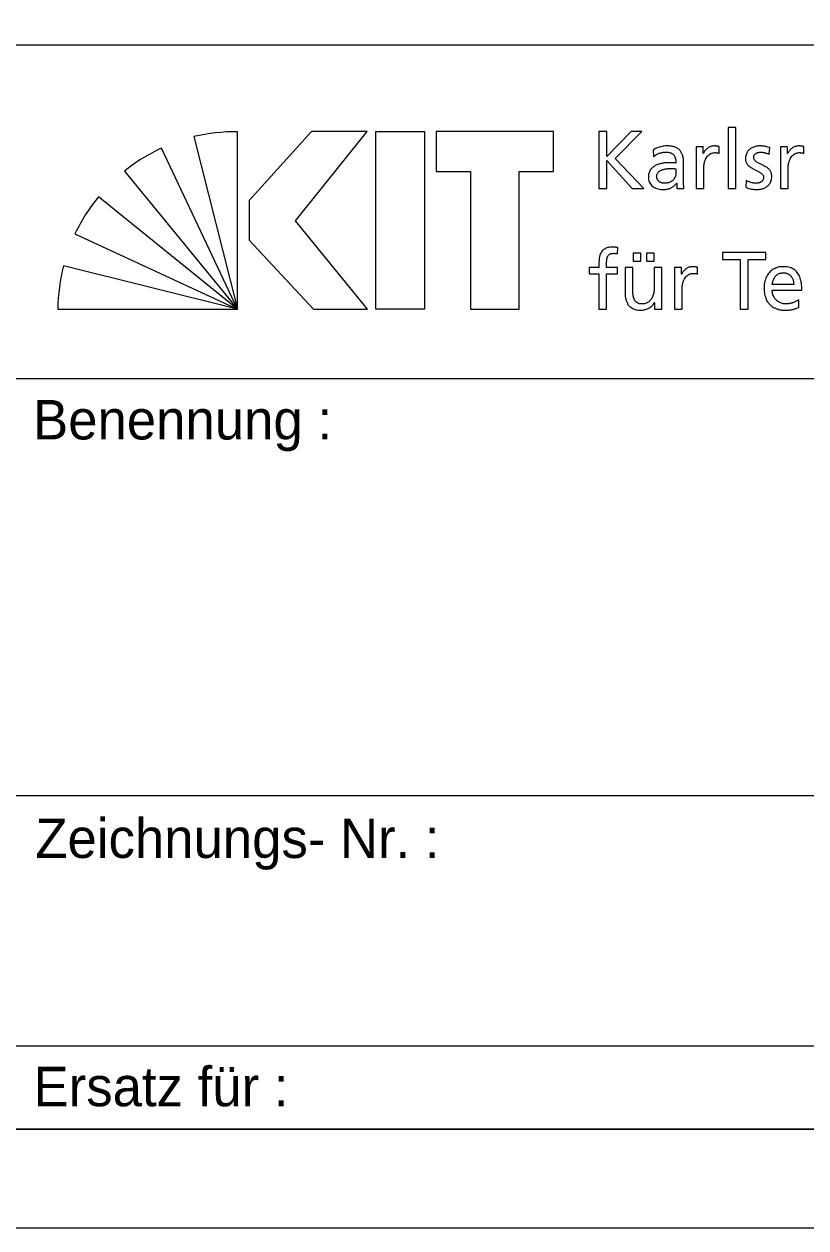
# Model space of a CAD drawing. Extents: x 0 to 11.9, y 0 to 8.4.
# Drawn here: x 11.007 to 11.403, y 0 to 0.61 of the extents above; entities that cross this region are included whole.
import ezdxf

# ---------------------------------------------------------------- set-up
doc = ezdxf.new("R2010")
doc.units = 0
doc.layers.add('90_Plankopf', color=7, linetype='Continuous')

msp = doc.modelspace()

# ---------------------------------------------------------------- linework, layer by layer
at = {"layer": '90_Plankopf'}
for p, q in [((10.0612, 0.5999), (11.84, 0.5999)), ((10.0612, 0.5999), (11.84, 0.5999)), ((11.11481, 0.46586), (11.11481, 0.55584)), ((11.2981, 0.55586), (11.2981, 0.52706)), ((11.09275, 0.55333), (11.11481, 0.46586)), ((11.11481, 0.46586), (11.07633, 0.54752)), ((11.32579, 0.54662), (11.326, 0.54332)), ((11.35926, 0.54484), (11.35926, 0.54831)), ((11.38457, 0.54439), (11.3849, 0.54778)), ((11.40211, 0.54484), (11.40211, 0.54831)), ((11.34118, 0.53118), (11.34118, 0.53989)), ((11.05744, 0.53585), (11.11481, 0.46586)), ((11.3373, 0.53709), (11.3373, 0.53523)), ((11.37297, 0.53118), (11.37277, 0.52772)), ((11.2981, 0.52706), (11.30222, 0.52706)), ((11.31506, 0.52706), (11.32108, 0.52706)), ((11.11481, 0.46586), (11.04434, 0.52286)), ((11.0324, 0.50413), (11.11481, 0.46586)), ((11.30773, 0.49393), (11.3079, 0.49706)), ((11.11481, 0.46586), (11.02658, 0.48788)), ((11.34827, 0.48365), (11.34827, 0.48712)), ((11.39706, 0.47841), (11.38616, 0.47841)), ((11.38616, 0.47552), (11.40119, 0.47552)), ((11.39958, 0.46673), (11.39958, 0.47061)), ((11.02364, 0.46586), (11.11481, 0.46586)), ((11.00001, 0.4307), (11.84, 0.4307)), ((11.00001, 0.2192), (11.84, 0.2192)), ((11.00001, 0.0923), (11.84, 0.0923)), ((11.84, 0.05), (10.0612, 0.05)), ((10.178, 0.05), (11.84, 0.05)), ((10.178, 0.05), (11.84, 0.05))]:
    msp.add_line(p, q, dxfattribs=at)
for points in [[(0, 0), (11.89, 0), (11.89, 8.41), (0, 8.41)], [(0.25, 0.05), (11.84, 0.05), (11.84, 8.36), (0.25, 8.36)], [(11.18066, 0.55586), (11.15236, 0.55586), (11.12073, 0.52099), (11.12073, 0.50092), (11.15338, 0.46586), (11.18085, 0.46586), (11.14422, 0.51063)], [(11.2097, 0.55586), (11.2097, 0.46586), (11.18501, 0.46586), (11.18501, 0.55586)], [(11.21562, 0.55586), (11.21562, 0.5356), (11.23301, 0.5356), (11.23301, 0.46586), (11.25771, 0.46586), (11.25771, 0.5356), (11.2751, 0.5356), (11.2751, 0.55586)]]:
    msp.add_lwpolyline(points, close=True, dxfattribs=at)
for points in [[(11.32108, 0.52706), (11.30647, 0.54224), (11.32001, 0.55586), (11.31452, 0.55586), (11.30222, 0.54319), (11.30222, 0.55586), (11.2981, 0.55586)], [(11.36381, 0.52706), (11.36768, 0.52706), (11.36768, 0.55801), (11.36381, 0.55801), (11.36381, 0.52706)], [(11.35122, 0.54484), (11.35113, 0.54484), (11.35113, 0.5481), (11.3475, 0.5481), (11.3475, 0.52706), (11.35138, 0.52706), (11.35138, 0.53663)], [(11.39407, 0.54484), (11.39398, 0.54484), (11.39398, 0.5481), (11.39035, 0.5481), (11.39035, 0.52706), (11.39423, 0.52706), (11.39423, 0.53663)], [(11.30222, 0.52706), (11.30222, 0.54117), (11.31506, 0.52706)], [(11.33763, 0.52978), (11.33772, 0.52978), (11.33772, 0.52706), (11.34135, 0.52706)], [(11.3699, 0.46586), (11.37403, 0.46586), (11.37403, 0.49104), (11.38298, 0.49104), (11.38298, 0.49467), (11.36094, 0.49467), (11.36094, 0.49104), (11.3699, 0.49104), (11.3699, 0.46586)], [(11.29824, 0.48885), (11.29824, 0.48691), (11.29329, 0.48691), (11.29329, 0.48378), (11.29824, 0.48378), (11.29824, 0.46586), (11.30212, 0.46586), (11.30212, 0.48378), (11.30769, 0.48378), (11.30769, 0.48691), (11.30212, 0.48691), (11.30212, 0.48918)], [(11.31554, 0.49426), (11.31554, 0.49013), (11.31942, 0.49013), (11.31942, 0.49426), (11.31554, 0.49426)], [(11.32231, 0.49426), (11.32231, 0.49013), (11.32619, 0.49013), (11.32619, 0.49426), (11.32231, 0.49426)], [(11.31542, 0.47602), (11.31542, 0.48691), (11.31154, 0.48691), (11.31154, 0.47441)], [(11.33015, 0.46586), (11.33015, 0.48691), (11.32627, 0.48691), (11.32627, 0.47717)], [(11.34022, 0.48365), (11.34014, 0.48365), (11.34014, 0.48691), (11.33651, 0.48691), (11.33651, 0.46586), (11.34039, 0.46586), (11.34039, 0.47544)], [(11.32631, 0.46921), (11.32639, 0.46921), (11.32639, 0.46586), (11.33015, 0.46586)]]:
    msp.add_lwpolyline(points, dxfattribs=at)
for centre, start, end in [((11.11449, 0.46056), 89.80527, 103.18947), ((11.11662, 0.46118), 115.01261, 128.3968), ((11.11816, 0.46263), 140.78977, 154.17397), ((11.11891, 0.46438), 165.72225, 179.10644)]:
    msp.add_arc(centre, 0.09528, start, end, dxfattribs=at)
for points in [[(11.34118, 0.53989), (11.34119, 0.5418), (11.34091, 0.54341), (11.34033, 0.5447), (11.33975, 0.54599), (11.33884, 0.54696), (11.33759, 0.54762), (11.33635, 0.54827), (11.33472, 0.5486), (11.33272, 0.5486), (11.33138, 0.54859), (11.33014, 0.54841), (11.32898, 0.54804), (11.32782, 0.54768), (11.32676, 0.54721), (11.32579, 0.54662)], [(11.326, 0.54332), (11.32653, 0.54376), (11.32713, 0.54414), (11.32779, 0.54446), (11.32846, 0.54478), (11.32916, 0.54503), (11.3299, 0.5452), (11.33063, 0.54538), (11.33137, 0.54546), (11.3321, 0.54546), (11.33339, 0.54546), (11.33441, 0.54526), (11.33518, 0.54485), (11.33594, 0.54444), (11.33649, 0.54383), (11.33682, 0.54302), (11.33715, 0.54219), (11.33731, 0.54118), (11.3373, 0.53997)], [(11.35926, 0.54831), (11.35899, 0.54837), (11.35873, 0.54841), (11.35849, 0.54846), (11.35824, 0.5485), (11.35798, 0.54854), (11.35769, 0.54856), (11.35741, 0.54859), (11.35708, 0.5486), (11.3567, 0.5486), (11.35595, 0.54859), (11.35523, 0.54843), (11.35452, 0.54811), (11.35382, 0.54779), (11.35318, 0.54736), (11.35261, 0.54679), (11.35203, 0.54623), (11.35157, 0.54558), (11.35122, 0.54484)], [(11.35138, 0.53663), (11.35139, 0.5384), (11.35163, 0.53993), (11.3521, 0.54121), (11.35257, 0.54249), (11.35323, 0.54348), (11.35409, 0.54416), (11.35494, 0.54486), (11.35595, 0.54521), (11.35712, 0.54521), (11.35746, 0.54522), (11.3578, 0.54519), (11.35818, 0.54514), (11.35855, 0.54509), (11.35891, 0.54499), (11.35926, 0.54484)], [(11.3849, 0.54778), (11.38414, 0.54801), (11.38337, 0.5482), (11.38259, 0.54836), (11.38181, 0.54851), (11.38097, 0.54859), (11.38007, 0.5486), (11.37903, 0.5486), (11.37805, 0.54847), (11.37716, 0.5482), (11.37625, 0.54794), (11.37547, 0.54753), (11.3748, 0.547), (11.37412, 0.54647), (11.37359, 0.54579), (11.37322, 0.54498), (11.37284, 0.54417), (11.37265, 0.54321), (11.37264, 0.54212), (11.37265, 0.54128), (11.37282, 0.54056), (11.37315, 0.53994), (11.37347, 0.53933), (11.37391, 0.5388), (11.37445, 0.53834), (11.375, 0.5379), (11.37559, 0.5375), (11.37623, 0.53715), (11.37688, 0.5368), (11.37753, 0.53647), (11.37817, 0.53617), (11.37882, 0.53586), (11.37942, 0.53555), (11.37995, 0.53522), (11.3805, 0.5349), (11.38093, 0.53454), (11.38126, 0.53413), (11.38158, 0.53373), (11.38176, 0.53325), (11.38176, 0.53271), (11.38176, 0.53215), (11.38163, 0.53167), (11.38139, 0.53128), (11.38116, 0.5309), (11.38084, 0.53059), (11.38045, 0.53035), (11.38006, 0.53012), (11.37963, 0.52995), (11.37917, 0.52985), (11.37871, 0.52975), (11.37825, 0.5297), (11.3778, 0.5297), (11.37742, 0.5297), (11.37695, 0.52975), (11.37639, 0.52986), (11.37584, 0.52997), (11.37526, 0.53014), (11.37466, 0.53036), (11.37405, 0.53058), (11.3735, 0.53085), (11.37297, 0.53118)], [(11.37277, 0.52772), (11.37366, 0.52726), (11.3746, 0.52694), (11.37558, 0.52678), (11.37656, 0.52662), (11.37755, 0.52655), (11.37854, 0.52656), (11.37949, 0.52656), (11.3804, 0.52669), (11.38127, 0.52695), (11.38215, 0.52722), (11.38293, 0.52762), (11.38363, 0.52816), (11.38431, 0.52869), (11.38487, 0.52938), (11.38527, 0.5302), (11.38568, 0.53103), (11.38588, 0.532), (11.38589, 0.53312), (11.38588, 0.53408), (11.38571, 0.53489), (11.38539, 0.53556), (11.38506, 0.53622), (11.38462, 0.53679), (11.38408, 0.53726), (11.38354, 0.53772), (11.38295, 0.53811), (11.3823, 0.53845), (11.38165, 0.53878), (11.38101, 0.53909), (11.38036, 0.53937), (11.37971, 0.53966), (11.37912, 0.53995), (11.37858, 0.54026), (11.37804, 0.54058), (11.3776, 0.54095), (11.37727, 0.54136), (11.37695, 0.54179), (11.37678, 0.5423), (11.37677, 0.54291), (11.37678, 0.54348), (11.37696, 0.54396), (11.37729, 0.54434), (11.37763, 0.54472), (11.37808, 0.545), (11.37864, 0.54519), (11.3792, 0.54538), (11.37982, 0.54546), (11.38048, 0.54546), (11.38072, 0.54546), (11.38102, 0.54543), (11.38139, 0.54538), (11.38175, 0.54531), (11.38213, 0.54523), (11.38254, 0.54513), (11.38295, 0.54503), (11.38333, 0.54491), (11.38369, 0.54478), (11.38405, 0.54466), (11.38434, 0.54453), (11.38457, 0.54439)], [(11.40211, 0.54831), (11.40184, 0.54837), (11.40158, 0.54841), (11.40134, 0.54846), (11.4011, 0.5485), (11.40083, 0.54854), (11.40054, 0.54856), (11.40026, 0.54859), (11.39993, 0.5486), (11.39955, 0.5486), (11.3988, 0.54859), (11.39808, 0.54843), (11.39737, 0.54811), (11.39667, 0.54779), (11.39603, 0.54736), (11.39546, 0.54679), (11.39488, 0.54623), (11.39442, 0.54558), (11.39407, 0.54484)], [(11.39423, 0.53663), (11.39424, 0.5384), (11.39448, 0.53993), (11.39495, 0.54121), (11.39542, 0.54249), (11.39608, 0.54348), (11.39694, 0.54416), (11.39779, 0.54486), (11.3988, 0.54521), (11.39997, 0.54521), (11.4003, 0.54522), (11.40065, 0.54519), (11.40103, 0.54514), (11.4014, 0.54509), (11.40175, 0.54499), (11.40211, 0.54484)], [(11.3373, 0.53997), (11.3368, 0.54), (11.33633, 0.54002), (11.33589, 0.54003), (11.33546, 0.54004), (11.33502, 0.54005), (11.33459, 0.54006), (11.33415, 0.54006), (11.33368, 0.54006), (11.33318, 0.54006), (11.33237, 0.54006), (11.33151, 0.53999), (11.33063, 0.53984), (11.32973, 0.5397), (11.32886, 0.53947), (11.32801, 0.53914), (11.32715, 0.53881), (11.32638, 0.53838), (11.32569, 0.53785), (11.32499, 0.53731), (11.32444, 0.53665), (11.32403, 0.53588), (11.32362, 0.53509), (11.32341, 0.53418), (11.3234, 0.53312), (11.32341, 0.5316), (11.32374, 0.53035), (11.32439, 0.52939), (11.32504, 0.52842), (11.32594, 0.5277), (11.3271, 0.52724), (11.32825, 0.52679), (11.32959, 0.52656), (11.33111, 0.52656), (11.332, 0.52657), (11.3328, 0.52668), (11.3335, 0.52689), (11.33421, 0.52709), (11.33483, 0.52736), (11.33536, 0.52769), (11.3359, 0.52802), (11.33635, 0.52837), (11.33673, 0.52874), (11.3371, 0.52911), (11.33741, 0.52945), (11.33763, 0.52978)], [(11.3373, 0.53523), (11.3373, 0.53418), (11.33708, 0.53323), (11.33664, 0.5324), (11.3362, 0.53157), (11.33554, 0.53092), (11.33467, 0.53043), (11.3338, 0.52995), (11.33272, 0.5297), (11.33144, 0.5297), (11.331, 0.5297), (11.33054, 0.52978), (11.33008, 0.52992), (11.32963, 0.53007), (11.3292, 0.53028), (11.32882, 0.53057), (11.32843, 0.53087), (11.32812, 0.53123), (11.32789, 0.53165), (11.32765, 0.53207), (11.32753, 0.53257), (11.32752, 0.53312), (11.32754, 0.53386), (11.32772, 0.53448), (11.32808, 0.53497), (11.32844, 0.53546), (11.32891, 0.53586), (11.32949, 0.53615), (11.33007, 0.53645), (11.33069, 0.53667), (11.33135, 0.53682), (11.33201, 0.53696), (11.33265, 0.53706), (11.33326, 0.53711), (11.33387, 0.53715), (11.33439, 0.53717), (11.33483, 0.53717), (11.33524, 0.53717), (11.33565, 0.53715), (11.33607, 0.53713), (11.33648, 0.53711), (11.33689, 0.53709), (11.3373, 0.53709)], [(11.34135, 0.52706), (11.34132, 0.52726), (11.34129, 0.52753), (11.34126, 0.52787), (11.34125, 0.52821), (11.34122, 0.52865), (11.34121, 0.52919), (11.34119, 0.52973), (11.34118, 0.53039), (11.34118, 0.53118)], [(11.3079, 0.49706), (11.30751, 0.49712), (11.3071, 0.49719), (11.30668, 0.49723), (11.30625, 0.49728), (11.30579, 0.49731), (11.3053, 0.49731), (11.30388, 0.4973), (11.3027, 0.4971), (11.30178, 0.49671), (11.30086, 0.49631), (11.30014, 0.49574), (11.29962, 0.495), (11.2991, 0.49426), (11.29875, 0.49337), (11.29854, 0.49233), (11.29833, 0.49129), (11.29824, 0.49014), (11.29824, 0.48885)], [(11.30212, 0.48918), (11.30212, 0.4899), (11.30216, 0.49056), (11.30224, 0.49116), (11.30232, 0.49177), (11.30249, 0.4923), (11.30275, 0.49275), (11.303, 0.4932), (11.30338, 0.49355), (11.30388, 0.49379), (11.30439, 0.49404), (11.30505, 0.49417), (11.30588, 0.49417), (11.30621, 0.49417), (11.30655, 0.49415), (11.30688, 0.49411), (11.30722, 0.49407), (11.3075, 0.49401), (11.30773, 0.49393)], [(11.34827, 0.48712), (11.348, 0.48717), (11.34774, 0.48722), (11.3475, 0.48727), (11.34725, 0.48731), (11.34698, 0.48734), (11.3467, 0.48737), (11.34642, 0.48739), (11.34609, 0.4874), (11.34571, 0.4874), (11.34496, 0.4874), (11.34423, 0.48724), (11.34352, 0.48692), (11.34282, 0.4866), (11.34218, 0.48616), (11.34161, 0.4856), (11.34104, 0.48503), (11.34057, 0.48439), (11.34022, 0.48365)], [(11.34039, 0.47544), (11.34039, 0.47721), (11.34064, 0.47873), (11.3411, 0.48001), (11.34158, 0.48129), (11.34224, 0.48228), (11.3431, 0.48297), (11.34395, 0.48367), (11.34496, 0.48401), (11.34612, 0.48402), (11.34646, 0.48403), (11.34681, 0.484), (11.34718, 0.48395), (11.34756, 0.48389), (11.34791, 0.48379), (11.34827, 0.48365)], [(11.40119, 0.47552), (11.40119, 0.47722), (11.40103, 0.4788), (11.40072, 0.48023), (11.40041, 0.48168), (11.39989, 0.48293), (11.39918, 0.484), (11.39846, 0.48507), (11.39751, 0.48591), (11.39631, 0.4865), (11.39512, 0.48709), (11.39365, 0.4874), (11.3919, 0.4874), (11.39041, 0.4874), (11.38906, 0.48714), (11.38785, 0.48662), (11.38665, 0.4861), (11.38561, 0.48537), (11.38474, 0.48442), (11.38387, 0.48347), (11.38321, 0.48235), (11.38275, 0.48105), (11.38228, 0.47976), (11.38205, 0.47833), (11.38204, 0.47676), (11.38204, 0.47504), (11.38225, 0.47348), (11.38269, 0.47209), (11.38312, 0.47069), (11.38379, 0.4695), (11.38469, 0.4685), (11.38558, 0.46749), (11.38671, 0.46672), (11.38808, 0.46619), (11.38945, 0.46564), (11.39107, 0.46538), (11.39293, 0.46537), (11.39408, 0.46538), (11.39506, 0.46545), (11.39587, 0.4656), (11.39667, 0.46575), (11.39737, 0.46593), (11.39797, 0.46614), (11.39855, 0.46634), (11.39909, 0.46654), (11.39958, 0.46673)], [(11.38616, 0.47841), (11.38623, 0.4791), (11.38639, 0.47978), (11.38664, 0.48047), (11.38688, 0.48116), (11.38722, 0.48179), (11.38768, 0.48236), (11.38812, 0.48294), (11.38869, 0.48339), (11.38937, 0.48374), (11.39006, 0.48408), (11.39087, 0.48426), (11.39182, 0.48427), (11.39266, 0.48426), (11.3934, 0.48411), (11.39404, 0.48381), (11.3947, 0.4835), (11.39524, 0.48309), (11.39569, 0.48255), (11.39614, 0.48201), (11.39648, 0.48139), (11.39671, 0.48069), (11.39694, 0.47998), (11.39706, 0.47922), (11.39706, 0.47841)], [(11.32627, 0.47717), (11.32627, 0.47589), (11.32615, 0.47471), (11.32589, 0.47365), (11.32564, 0.4726), (11.32525, 0.47169), (11.32473, 0.47092), (11.32421, 0.47015), (11.32354, 0.46956), (11.32273, 0.46914), (11.32193, 0.46872), (11.32097, 0.46851), (11.31987, 0.4685), (11.31875, 0.46857), (11.31786, 0.46889), (11.31721, 0.46945), (11.31656, 0.47002), (11.3161, 0.47084), (11.31582, 0.47193), (11.31554, 0.47302), (11.31541, 0.47438), (11.31542, 0.47602)], [(11.31154, 0.47441), (11.31154, 0.47251), (11.31181, 0.4709), (11.31237, 0.46955), (11.31293, 0.4682), (11.31379, 0.46717), (11.31496, 0.46645), (11.31612, 0.46574), (11.31761, 0.46538), (11.31942, 0.46537), (11.3204, 0.46538), (11.32135, 0.46553), (11.32225, 0.46583), (11.32315, 0.46614), (11.32396, 0.46658), (11.32466, 0.46715), (11.32537, 0.46772), (11.32592, 0.46841), (11.32631, 0.46921)], [(11.39958, 0.47061), (11.39933, 0.47041), (11.39899, 0.47019), (11.39852, 0.46995), (11.39806, 0.46971), (11.39754, 0.46948), (11.39694, 0.46926), (11.39634, 0.46904), (11.39572, 0.46886), (11.39506, 0.46872), (11.3944, 0.46858), (11.39374, 0.46851), (11.39309, 0.4685), (11.39217, 0.46851), (11.3913, 0.46868), (11.39046, 0.46902), (11.38964, 0.46935), (11.38889, 0.46983), (11.38825, 0.47045), (11.38761, 0.47107), (11.3871, 0.47181), (11.38673, 0.47267), (11.38636, 0.47353), (11.38617, 0.47448), (11.38616, 0.47552)]]:
    msp.add_open_spline(points, degree=3, dxfattribs=at)

# ---------------------------------------------------------------- texts
for s, p in [('Benennung :', (11.01113, 0.39979)), ('Zeichnungs- Nr. :', (11.01227, 0.18758)), ('Ersatz für :', (11.01139, 0.06169))]:
    msp.add_text(s, height=0.02, dxfattribs=at).set_placement(p)

doc.saveas('drawing.dxf')
